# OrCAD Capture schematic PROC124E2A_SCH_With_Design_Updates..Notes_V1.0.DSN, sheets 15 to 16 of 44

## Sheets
15 11. PERIPHERAL POWER SUPPLY-2: size C; title: PERIPHERAL POWER SUPPLY-2
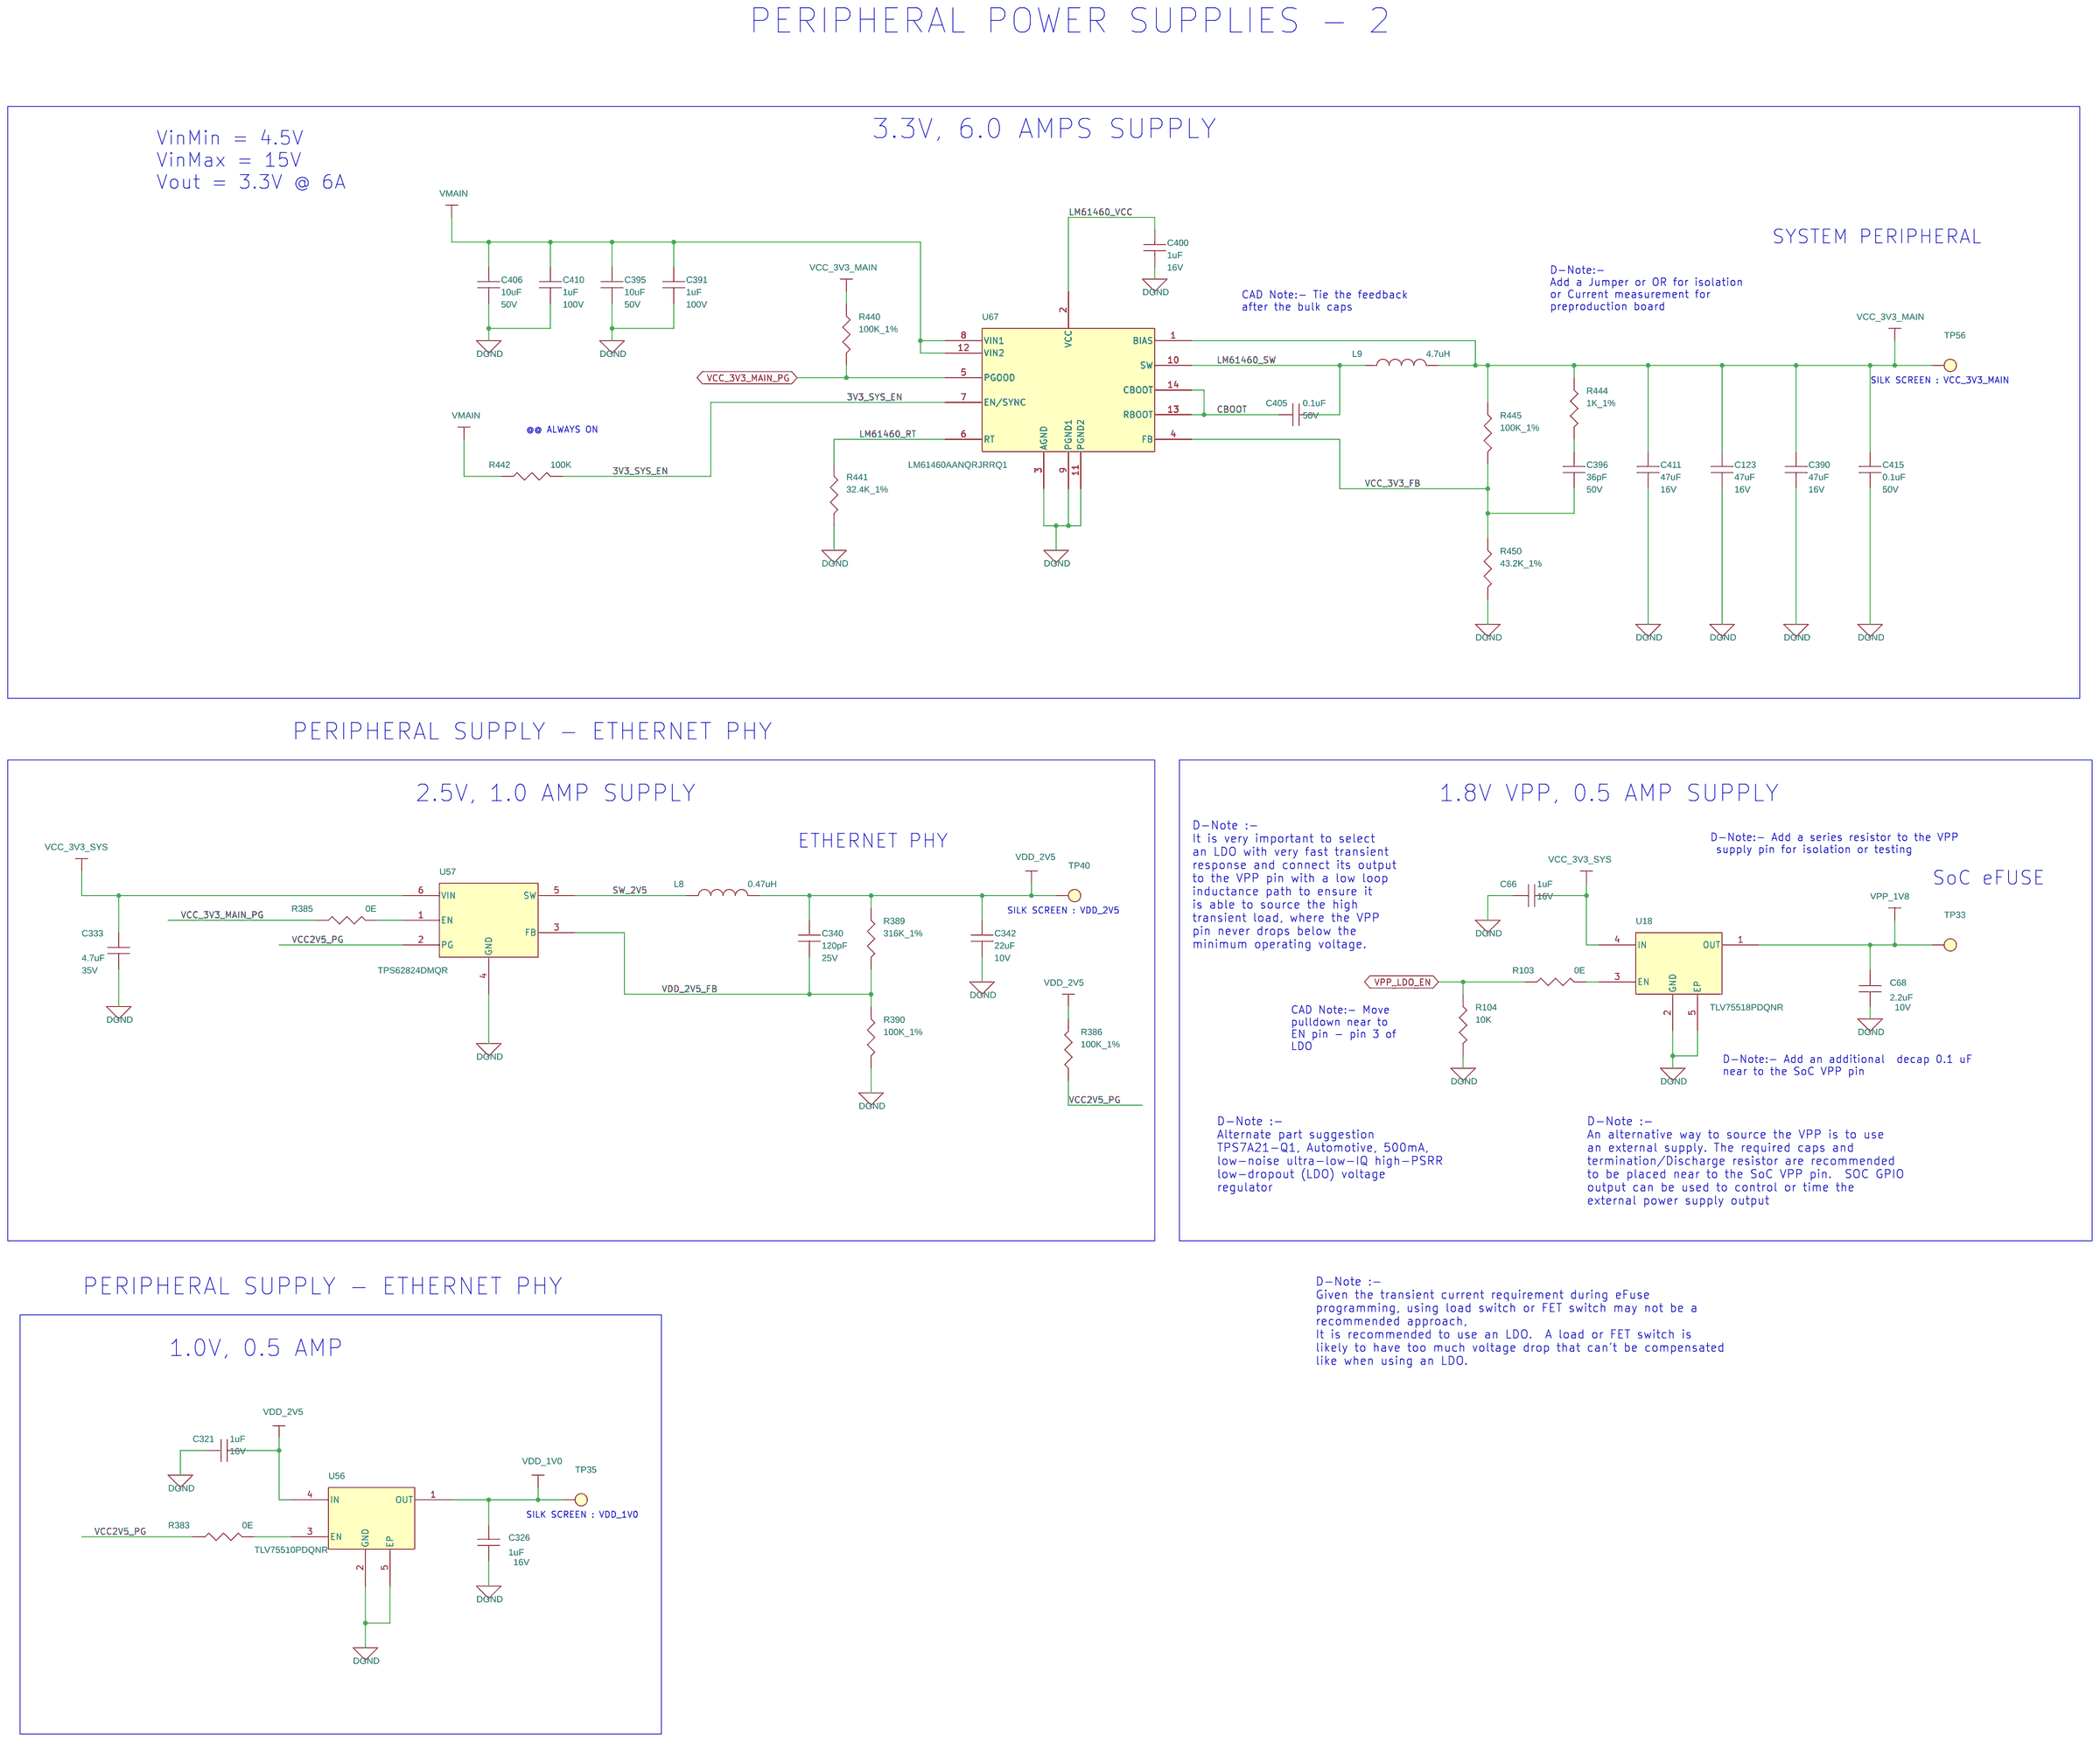
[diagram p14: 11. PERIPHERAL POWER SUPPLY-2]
16 13. CURRENT MONITORING DEVICES: size C; title: CURRENT MONITORING DEVICES
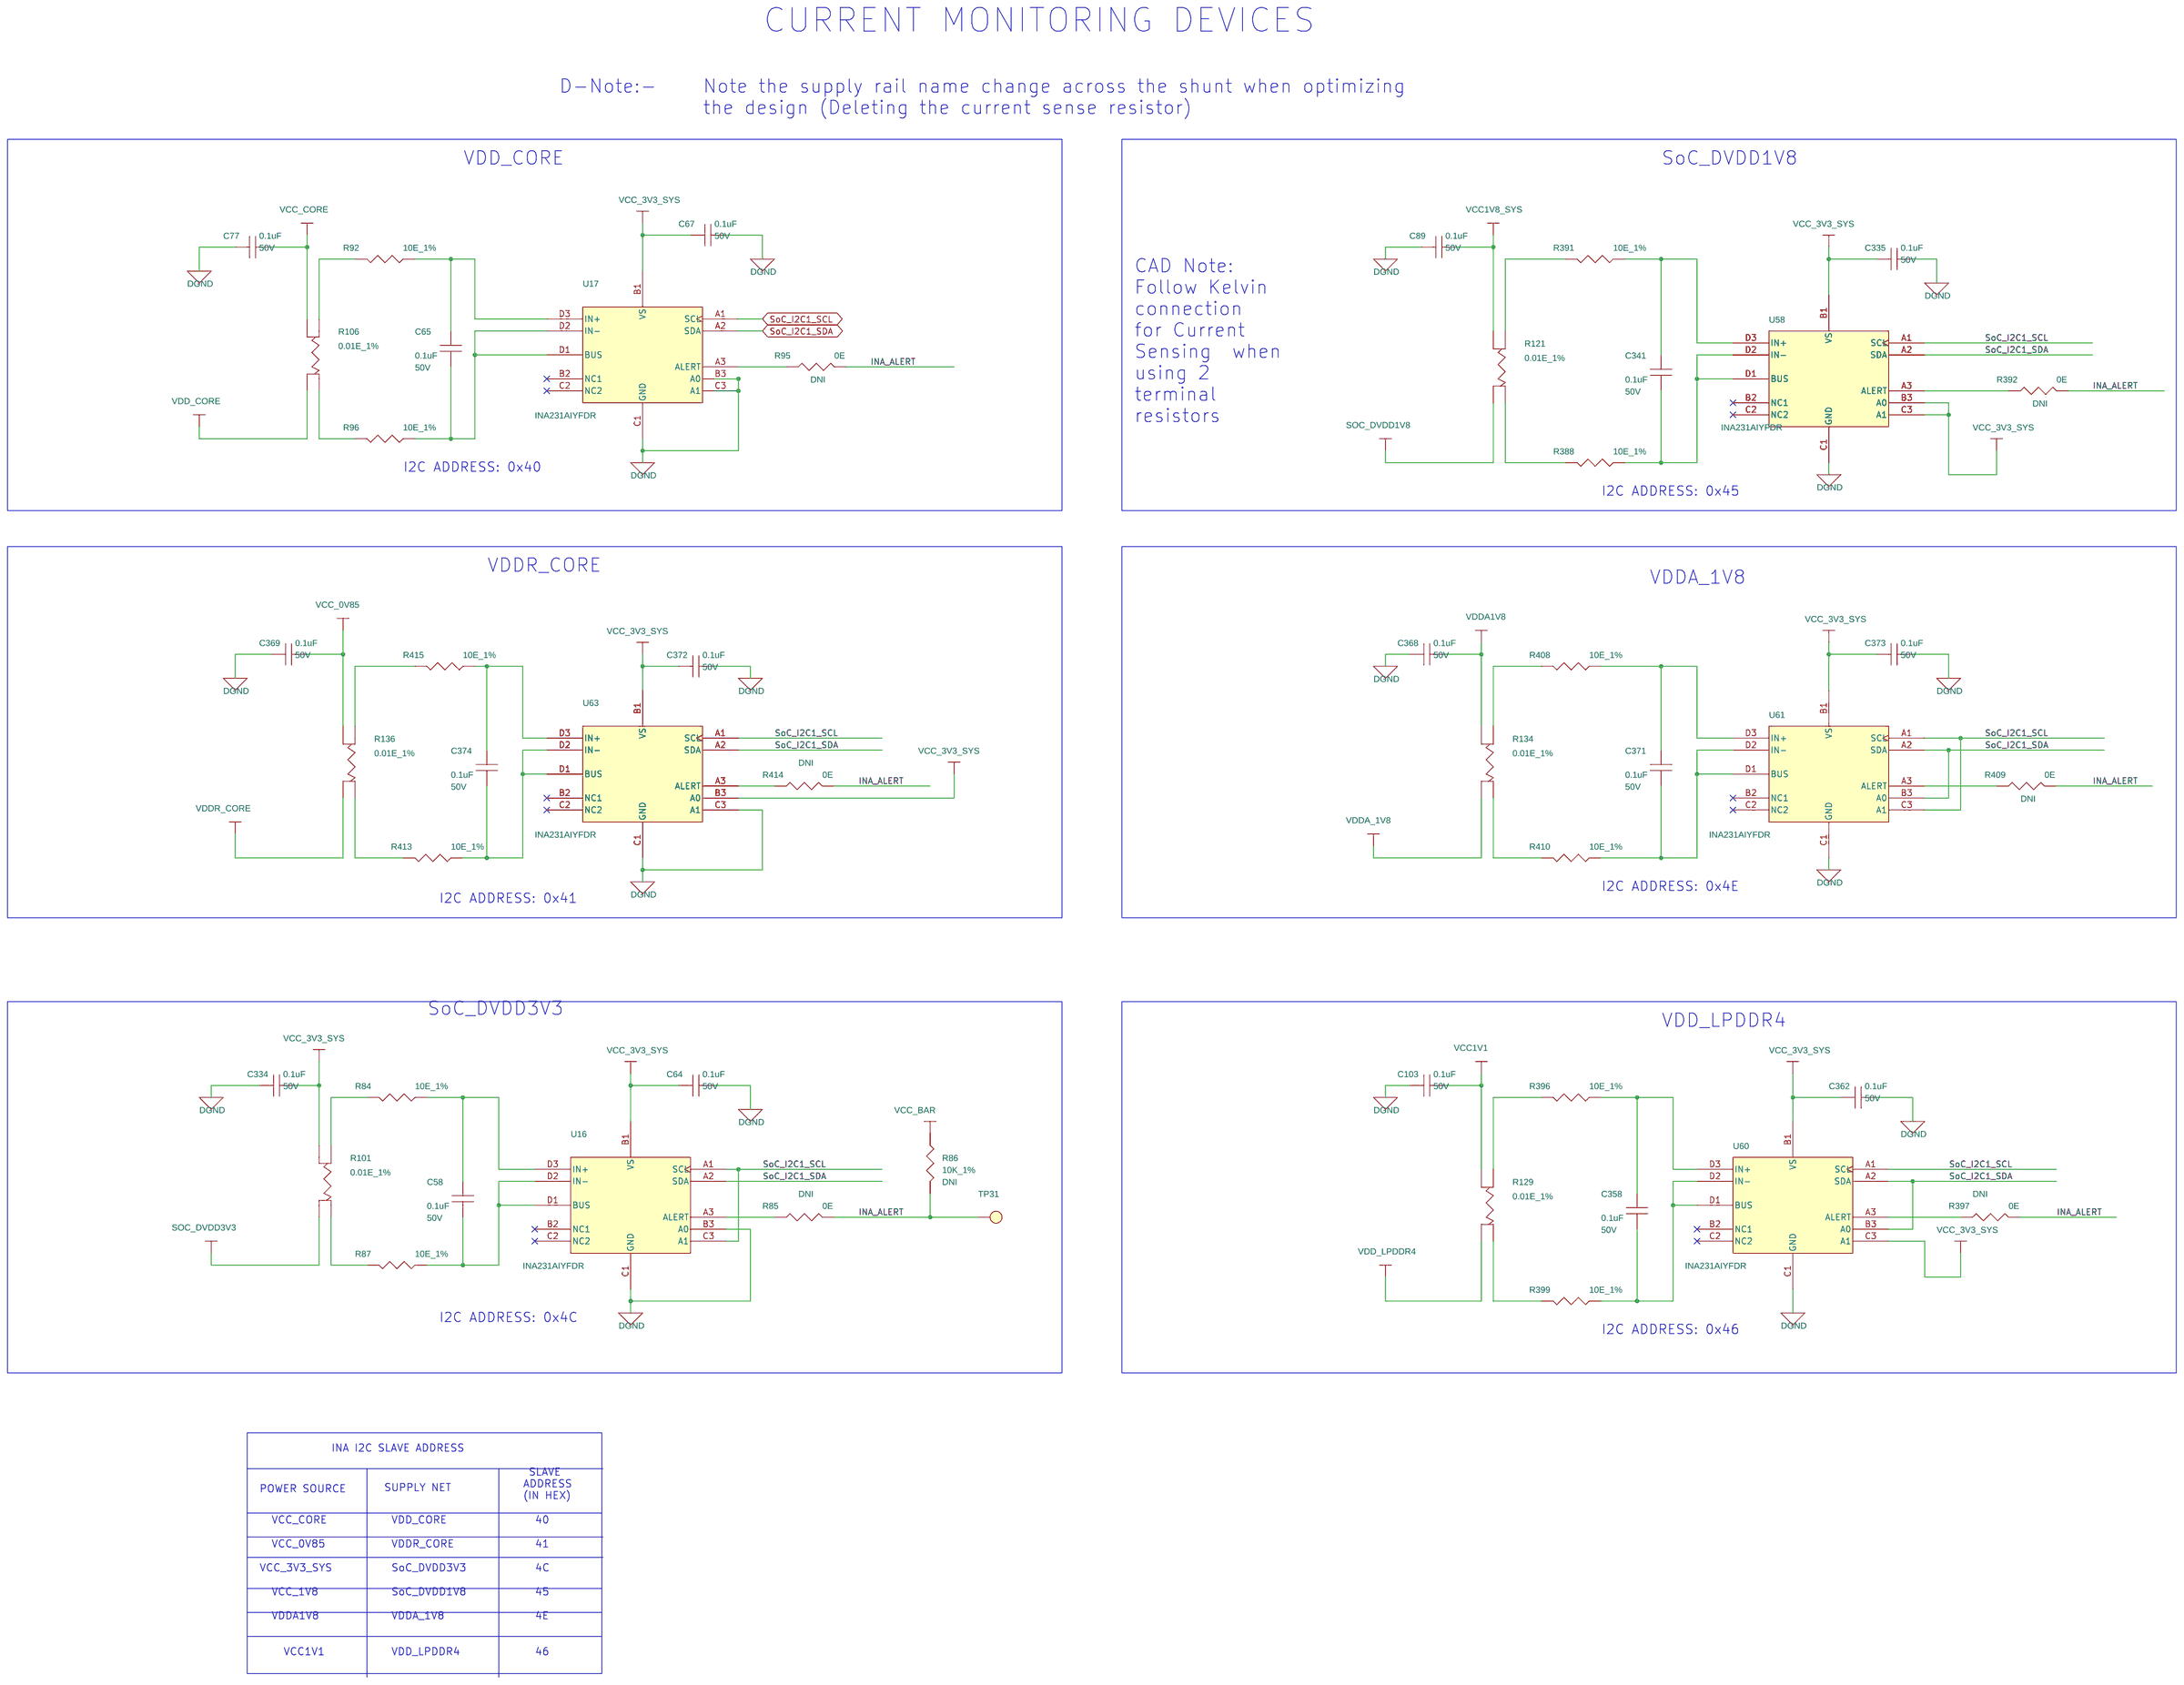
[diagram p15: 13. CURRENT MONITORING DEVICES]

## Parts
sheet 11. PERIPHERAL POWER SUPPLY-2
C66  1uF  [CAP0201_0-5]
C68  2.2uF  [CAP0201_0-5]
C123  47uF  [CAP1210_2-75]
C321  1uF  [CAP0201_0-5]
C326  1uF  [CAP0201_0-5]
C333  4.7uF  [CAP0603_1]
C340  120pF  [CAP0201_0-5]
C342  22uF  [CAP0603_1]
C390  47uF  [CAP1210_2-75]
C391  1uF  [CAP0805_1-5]
C395  10uF  [CAP0805_1-5]
C396  36pF  [CAP0402_0-75]
C400  1uF  [CAP0201_0-5]
C405  0.1uF  [CAP0402_0-75]
C406  10uF  [CAP0805_1-5]
C410  1uF  [CAP0805_1-5]
C411  47uF  [CAP1210_2-75]
C415  0.1uF  [CAP0402_0-75]
L8  0.47uH  [IND0806_1-2]
L9  4.7uH  [IND_XAL6060_260X270_SMD_6-1]
R103  0E  [RES0201_0-5]
R104  10K  [RES0201_0-5]
R383  0E  [RES0201_0-5]
R385  0E  [RES0201_0-5]
R386  100K_1%  [RES0402_0-5]
R389  316K_1%  [RES0402_0-5]
R390  100K_1%  [RES0402_0-5]
R440  100K_1%  [RES0402_0-5]
R441  32.4K_1%  [RES0402_0-5]
R442  100K  [RES0201_0-5]
R444  1K_1%  [RES0402_0-5]
R445  100K_1%  [RES0402_0-5]
R450  43.2K_1%  [RES0402_0-5]
TP33  TP20_SMD  [TP20_SMD]
TP35  TP20_SMD  [TP20_SMD]
TP40  TP20_SMD  [TP20_SMD]
TP56  TP20_SMD  [TP20_SMD]
U18  TLV75518PDQNR  [X2SON4_TLV71318P_40X40_0-4]
U56  TLV75510PDQNR  [X2SON4_TLV71318P_40X40_0-4]
U57  TPS62824DMQR  [VSONHR6_TPS62826_60X60_1]
U67  LM61460AANQRJRRQ1  [VQFNHR14_LM61460_160X140_1]
sheet 13. CURRENT MONITORING DEVICES
C58  0.1uF  [CAP0402_0-75]
C64  0.1uF  [CAP0402_0-75]
C65  0.1uF  [CAP0402_0-75]
C67  0.1uF  [CAP0402_0-75]
C77  0.1uF  [CAP0402_0-75]
C89  0.1uF  [CAP0402_0-75]
C103  0.1uF  [CAP0402_0-75]
C334  0.1uF  [CAP0402_0-75]
C335  0.1uF  [CAP0402_0-75]
C341  0.1uF  [CAP0402_0-75]
C358  0.1uF  [CAP0402_0-75]
C362  0.1uF  [CAP0402_0-75]
C368  0.1uF  [CAP0402_0-75]
C369  0.1uF  [CAP0402_0-75]
C371  0.1uF  [CAP0402_0-75]
C372  0.1uF  [CAP0402_0-75]
C373  0.1uF  [CAP0402_0-75]
C374  0.1uF  [CAP0402_0-75]
R84  10E_1%  [RES0402_0-5]
R85  0E  [RES0201_0-5]
R86  10K_1%  [RES0201_0-5]
R87  10E_1%  [RES0402_0-5]
R92  10E_1%  [RES0402_0-5]
R95  0E  [RES0201_0-5]
R96  10E_1%  [RES0402_0-5]
R101  0.01E_1%  [RES_KRL3216T4_1206-4_0-7]
R106  0.01E_1%  [RES_KRL3216T4_1206-4_0-7]
R121  0.01E_1%  [RES_KRL3216T4_1206-4_0-7]
R129  0.01E_1%  [RES_KRL3216T4_1206-4_0-7]
R134  0.01E_1%  [RES_KRL3216T4_1206-4_0-7]
R136  0.01E_1%  [RES_KRL3216T4_1206-4_0-7]
R388  10E_1%  [RES0402_0-5]
R391  10E_1%  [RES0402_0-5]
R392  0E  [RES0201_0-5]
R396  10E_1%  [RES0402_0-5]
R397  0E  [RES0201_0-5]
R399  10E_1%  [RES0402_0-5]
R408  10E_1%  [RES0402_0-5]
R409  0E  [RES0201_0-5]
R410  10E_1%  [RES0402_0-5]
R413  10E_1%  [RES0402_0-5]
R414  0E  [RES0201_0-5]
R415  10E_1%  [RES0402_0-5]
TP31  TP20_SMD  [TP20_SMD]
U16  INA231AIYFDR  [DSBGA12_15-74_60X70_0-4]
U17  INA231AIYFDR  [DSBGA12_15-74_60X70_0-4]
U58  INA231AIYFDR  [DSBGA12_15-74_60X70_0-4]
U60  INA231AIYFDR  [DSBGA12_15-74_60X70_0-4]
U61  INA231AIYFDR  [DSBGA12_15-74_60X70_0-4]
U63  INA231AIYFDR  [DSBGA12_15-74_60X70_0-4]

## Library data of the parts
C66 C321 C326 C400 = CAP: CAP CERAMIC 1uF 16V 20% X5R 0201; Chkd/date: MANIRAJA/300520; Crtd /date: ALVY/260520; Custom_Duty: 15%; Customs_HS_Code: 85322990; Distributor_name: DIGIKEY; Distributor_part_number: 490-18654-1-ND; Footprint Path: Y:\MIS_DATABASE\Library\ALTIUM_TOOL\PCB_FOOTPRINTS\Altium_Footprint_Lib.PcbLib; Height: 0.39MM; Library Path: Y:\MIS_DATABASE\Library\ALTIUM_TOOL\SCHEMATICS_PARTS\MS_DISCRETE_Library.schlib; Mfr_name: MURATA; Mfr_part_number: GRM033R61C105ME15D; Mistral Part No: 120018090038-R; Package: 0201; Part_type: CAPACITORS\CERAMIC; Project: QCS610_NANOSOM; RoHS: RoHS; Temperature: -55°C+85°C; Tolerance: 20%; Voltage: 16V; Wattage: NA; Weight: 0.33mg; Datasheet: Y:\MIS_DATABASE\DATASHEETS\CAPACITORS\GRM033R61C105ME15.PDF
C68 = CAP: CAP CERAMIC 2.2uF 10V 10% X5R 0201; Chkd/date: MANIRAJA/220918; Crtd /date: MANIRAJA/220918; Custom_Duty: 15%; Customs_HS_Code: 85322990; Distributor_name: DIGIKEY; Distributor_part_number: 490-13227-1-ND; Footprint Path: Y:\MIS_DATABASE\Library\ALTIUM_TOOL\PCB_FOOTPRINTS\Altium_Footprint_Lib.PcbLib; Height: 0.39MM; Library Path: Y:\MIS_DATABASE\Library\ALTIUM_TOOL\SCHEMATICS_PARTS\MS_DISCRETE_Library.schlib; Mfr_name: MURATA; Mfr_part_number: GRM033R61A225KE47D; Mistral Part No: 120018090044-R; Package: 0201; Part_type: CAPACITORS\CERAMIC; Project: TI_60GHz-AOP; RoHS: RoHS; Temperature: -55°C+85°C; Tolerance: 10%; Voltage: 10V; Wattage: NA; Weight: 0.33mg; Datasheet: Y:\MIS_DATABASE\DATASHEETS\CAPACITORS\GRM033R61A225KE47D.PDF
C123 C390 C411 = CAP: CAP CERAMIC 47uF 16V 10% X6S 1210; Chkd/date: ALVY/010721; Crtd /date: MANIRAJA/010721; Custom_Duty: 15%; Customs_HS_Code: 85322990; Distributor_name: DIGIKEY; Distributor_part_number: 490-10531-1-ND; Footprint Path: Y:\MIS_DATABASE\Library\ALTIUM_TOOL\PCB_FOOTPRINTS\Altium_Footprint_Lib.PcbLib; Height: 2.70MM; Library Path: Y:\MIS_DATABASE\Library\ALTIUM_TOOL\SCHEMATICS_PARTS\MS_DISCRETE_Library.schlib; Mfr_name: MURATA; Mfr_part_number: GRM32EC81C476KE15L; Mistral Part No: 120021070001-R; Package: 1210; Part_type: CAPACITORS\CERAMIC; Project: TI_AM263X_CC; RoHS: RoHS; Temperature: -55°C+105°C; Tolerance: 10%; Voltage: 16V; Wattage: NA; Weight: 100mg; Datasheet: Y:\MIS_DATABASE\DATASHEETS\CAPACITORS\GRM32EC81C476KE15.PDF
C333 = CAP: CAP CERAMIC 4.7uF 35V 20% X5R 0603; Chkd/date: MANIRAJA/120520; Crtd /date: ALVY/120520; Custom_Duty: 15%; Customs_HS_Code: 85322990; Distributor_name: DIGIKEY; Distributor_part_number: 490-11995-1-ND; Footprint Path: Y:\MIS_DATABASE\Library\ALTIUM_TOOL\PCB_FOOTPRINTS\Altium_Footprint_Lib.PcbLib; Height: 1.00MM; Library Path: Y:\MIS_DATABASE\Library\ALTIUM_TOOL\SCHEMATICS_PARTS\MS_DISCRETE_Library.schlib; Mfr_name: MURATA; Mfr_part_number: GRM188R6YA475ME15D; Mistral Part No: 120020050017-R; Package: 0603; Part_type: CAPACITORS\CERAMIC; Project: SD865_NANOSOM; RoHS: RoHS; Temperature: -55°C+85°C; Tolerance: 20%; Voltage: 35V; Wattage: NA; Weight: 6.3mg; Datasheet: Y:\MIS_DATABASE\DATASHEETS\CAPACITORS\GRM188R6YA475ME15.PDF
C340 = CAP: CAP CERAMIC 120pF 25V 10% X7R 0201; Chkd/date: ALVY/260821; Crtd /date: MANIRAJA/260821; Custom_Duty: 15%; Customs_HS_Code: 85322990; Distributor_name: DIGIKEY; Distributor_part_number: 490-3173-1-ND; Footprint Path: Y:\MIS_DATABASE\Library\ALTIUM_TOOL\PCB_FOOTPRINTS\Altium_Footprint_Lib.PcbLib; Height: 0.33MM; Library Path: Y:\MIS_DATABASE\Library\ALTIUM_TOOL\SCHEMATICS_PARTS\MS_DISCRETE_Library.schlib; Mfr_name: MURATA; Mfr_part_number: GRM033R71E121KA01D; Mistral Part No: 120021080009-R; Package: 0201; Part_type: CAPACITORS\CERAMIC; Project: TI_AM62x SKEVM_BRD; RoHS: RoHS; Temperature: -55°C+125°C; Tolerance: 10%; Voltage: 25V; Wattage: NA; Weight: 0.33mg; Datasheet: Y:\MIS_DATABASE\DATASHEETS\CAPACITORS\GRM033R71E121KA01.PDF
C342 = CAP: CAP CERAMIC 22uF 10V 20% X5R 0603; Chkd/date: MANIRAJA/230118; Crtd /date: MANIRAJA/230118; Custom_Duty: 15%; Customs_HS_Code: 85322990; Distributor_name: DIGIKEY; Distributor_part_number: 490-10476-1-ND; Footprint Path: Y:\MIS_DATABASE\Library\ALTIUM_TOOL\PCB_FOOTPRINTS\Altium_Footprint_Lib.PcbLib; Height: 1.00MM; Library Path: Y:\MIS_DATABASE\Library\ALTIUM_TOOL\SCHEMATICS_PARTS\MS_DISCRETE_Library.schlib; Mfr_name: MURATA; Mfr_part_number: GRM188R61A226ME15D; Mistral Part No: 120014100009-R; Package: 0603; Part_type: CAPACITORS\CERAMIC; Project: TI_MAXIE_CPB; RoHS: RoHS; Temperature: -55°C+85°C; Tolerance: 20%; Voltage: 10V; Wattage: NA; Weight: 6.3mg; Datasheet: Y:\MIS_DATABASE\DATASHEETS\CAPACITORS\GRM188R61A226ME15.PDF
C391 C410 = CAP: CAP CERAMIC 1uF 100V 10% X7S 0805; Chkd/date: MANIRAJA/160921; Crtd /date: ALVY/150921; Custom_Duty: 15%; Customs_HS_Code: 85322990; Distributor_name: DIGIKEY; Distributor_part_number: 490-14464-1-ND; Footprint Path: Y:\MIS_DATABASE\Library\ALTIUM_TOOL\PCB_FOOTPRINTS\Altium_Footprint_Lib.PcbLib; Height: 1.45MM; Library Path: Y:\MIS_DATABASE\Library\ALTIUM_TOOL\SCHEMATICS_PARTS\MS_DISCRETE_Library.schlib; Mfr_name: MURATA; Mfr_part_number: GRM21BC72A105KE01L; Mistral Part No: 120013030002-R; Package: 0805; Part_type: CAPACITORS\CERAMIC; Project: TI_AM62x SKEVM_BRD; RoHS: RoHS; Temperature: -55°C+125°C; Tolerance: 10%; Voltage: 100V; Wattage: NA; Weight: 6.4mg; Datasheet: Y:\MIS_DATABASE\DATASHEETS\CAPACITORS\GRM21BC72A105KE01.PDF
C395 C406 = CAP: CAP CERAMIC 10uF 50V 10% X5R 0805; Chkd/date: MANIRAJA/010321; Crtd /date: ALVY/010321; Custom_Duty: 15%; Customs_HS_Code: 85322990; Distributor_name: DIGIKEY; Distributor_part_number: 490-18663-1-ND; Footprint Path: Y:\MIS_DATABASE\Library\ALTIUM_TOOL\PCB_FOOTPRINTS\Altium_Footprint_Lib.PcbLib; Height: 1.45MM; Library Path: Y:\MIS_DATABASE\Library\ALTIUM_TOOL\SCHEMATICS_PARTS\MS_DISCRETE_Library.schlib; Mfr_name: MURATA; Mfr_part_number: GRM21BR61H106KE43L; Mistral Part No: 120021030002-R; Package: 0805; Part_type: CAPACITORS\CERAMIC; Project: J7ES_SK_BRD; RoHS: RoHS; Temperature: -55°C+85°C; Tolerance: 10%; Voltage: 50V; Wattage: NA; Weight: 6.4mg; Datasheet: Y:\MIS_DATABASE\DATASHEETS\CAPACITORS\GRM21BR61H106KE43.PDF
C396 = CAP: CAP CERAMIC 36pF 50V 2% HI-Q C0G(NP0) 0402; Chkd/date: MANIRAJA/061021; Crtd /date: ALVY/051021; Custom_Duty: 15%; Customs_HS_Code: 85322990; Distributor_name: DIGIKEY; Distributor_part_number: 490-GJM1555C1H360GB01DTR-ND; Footprint Path: Y:\MIS_DATABASE\Library\ALTIUM_TOOL\PCB_FOOTPRINTS\Altium_Footprint_Lib.PcbLib; Height: 0.55MM; Library Path: Y:\MIS_DATABASE\Library\ALTIUM_TOOL\SCHEMATICS_PARTS\MS_DISCRETE_Library.schlib; Mfr_name: MURATA; Mfr_part_number: GJM1555C1H360GB01D; Mistral Part No: 120021100002-R; Package: 0402; Part_type: CAPACITORS\CERAMIC; Project: TI_AM62x SKEVM_BRD; RoHS: RoHS; Temperature: -55°C+125°C; Tolerance: 2%; Voltage: 50V; Wattage: NA; Weight: 1.5mg; Datasheet: Y:\MIS_DATABASE\DATASHEETS\CAPACITORS\GJM1555C1H360GB01.PDF
C405 C415 = CAP: CAP CERAMIC 0.1uF 50V 10% X7R 0402; Chkd/date: MANIRAJA/261020; Crtd /date: ALVY/211020; Custom_Duty: 15%; Customs_HS_Code: 85322990; Distributor_name: DIGIKEY; Distributor_part_number: 490-10700-1-ND; Footprint Path: Y:\MIS_DATABASE\Library\ALTIUM_TOOL\PCB_FOOTPRINTS\Altium_Footprint_Lib.PcbLib; Height: 0.55MM; Library Path: Y:\MIS_DATABASE\Library\ALTIUM_TOOL\SCHEMATICS_PARTS\MS_DISCRETE_Library.schlib; Mfr_name: MURATA; Mfr_part_number: GRM155R71H104KE14D; Mistral Part No: 120011100014-R; Package: 0402; Part_type: CAPACITORS\CERAMIC; Project: J7_CP; RoHS: RoHS; Temperature: -55°C+125°C; Tolerance: 10%; Voltage: 50V; Wattage: NA; Weight: 3.1mg; Datasheet: Y:\MIS_DATABASE\DATASHEETS\CAPACITORS\GRM155R71H104KE14.PDF
L8 = INDUCTOR: IND CHIP 0.47uH 4.5A 20% 0806; Chkd/date: MANIRAJA/121020; Crtd /date: ALVY/121020; Custom_Duty: 24%; Customs_HS_Code: 85437099; Distributor_name: DIGIKEY; Distributor_part_number: DFE201612E-R47M=P2-ND; Footprint Path: Y:\MIS_DATABASE\Library\ALTIUM_TOOL\PCB_FOOTPRINTS\Altium_Footprint_Lib.PcbLib; Height: 1.20MM; Library Path: Y:\MIS_DATABASE\Library\ALTIUM_TOOL\SCHEMATICS_PARTS\MS_DISCRETE_Library.schlib; Mfr_name: MURATA; Mfr_part_number: DFE201612E-R47M=P2; Mistral Part No: 130020100030-R; Package: 0806; Project: AM64X_SKEVM; RoHS: RoHS; Temperature: -40°C+125°C; Tolerance: 20%; Voltage: NA; Wattage: NA; Weight: 18.8mg; Datasheet: Y:\MIS_DATABASE\DATASHEETS\DISCRETES\INDUCTORS\DFE201612E.PDF
L9 = INDUCTOR: IND POWER 4.7uH 11A 20% SMD; Chkd/date: VASANTHA/090317; Crtd /date: MANIRAJA/090317; Custom_Duty: 15%; Customs_HS_Code: 85412900; Distributor_name: MOUSER; Distributor_part_number: 994-XAL6060-472MEB; Footprint Path: Y:\MIS_DATABASE\Library\ALTIUM_TOOL\PCB_FOOTPRINTS\Altium_Footprint_Lib.PcbLib; Height: 6.10MM; Library Path: Y:\MIS_DATABASE\Library\ALTIUM_TOOL\SCHEMATICS_PARTS\MS_DISCRETE_Library.schlib; Mfr_name: COILCRAFT; Mfr_part_number: XAL6060-472MEB; Mistral Part No: 130015090013-R; Package: SMD; Project: OCTBTS_3000; RoHS: RoHS; Temperature: -40°C+125°C; Tolerance: 20%; Voltage: NA; Wattage: NA; Weight: 1600g; Datasheet: Y:\MIS_DATABASE\DATASHEETS\DISCRETES\INDUCTORS\XAL6060-SER.PDF
R103 R383 R385 = RESISTOR: RES 0E 1/20W 5% 0201; Chkd/date: NAVEED/301214; Crtd /date: MUDDU/120710; Custom_Duty: 15%; Customs_HS_Code: 85332119; Distributor_name: DIGIKEY; Distributor_part_number: 311-0.0NCT-ND; Footprint Path: Y:\MIS_DATABASE\Library\ALTIUM_TOOL\PCB_FOOTPRINTS\Altium_Footprint_Lib.PcbLib; Height: 0.26MM; Library Path: Y:\MIS_DATABASE\Library\ALTIUM_TOOL\SCHEMATICS_PARTS\MS_DISCRETE_Library.schlib; Mfr_name: YAGEO AMERICA; Mfr_part_number: RC0201JR-070RL; Mistral Part No: 110010070067-R; Package: 0201; Part_type: RESISTORS\FIXED; Project: PB_BUGBASE; RoHS: RoHS; Temperature: -55°C+125°C; Tolerance: 5%; Voltage: NA; Wattage: 1/20W; Weight: 0.17mg; Datasheet: Y:\MIS_DATABASE\DATASHEETS\RESISTORS\RCXXXXL-SER_MAR18.PDF
R104 = RESISTOR: RES 10K 1/20W 5% 0201; Chkd/date: MANIRAJA/050517; Crtd /date: MANIRAJA/050517; Custom_Duty: 15%; Customs_HS_Code: 85332119; Distributor_name: DIGIKEY; Distributor_part_number: 311-10KNCT-ND; Footprint Path: Y:\MIS_DATABASE\Library\ALTIUM_TOOL\PCB_FOOTPRINTS\Altium_Footprint_Lib.PcbLib; Height: 0.26MM; Library Path: Y:\MIS_DATABASE\Library\ALTIUM_TOOL\SCHEMATICS_PARTS\MS_DISCRETE_Library.schlib; Mfr_name: YAGEO AMERICA; Mfr_part_number: RC0201JR-0710KL; Mistral Part No: 110010070051-R; Package: 0201; Part_type: RESISTORS\FIXED; Project: GOLDEN-I LITE; RoHS: RoHS; Temperature: -55°C+125°C; Tolerance: 5%; Voltage: NA; Wattage: 1/20W; Weight: 0.17mg; Datasheet: Y:\MIS_DATABASE\DATASHEETS\RESISTORS\RCXXXXL-SER_MAR18.PDF
R386 R390 R440 R445 = RESISTOR: RES 100K 1/10W 1% 0402; Chkd/date: VASANTHA/201216; Crtd /date: MAZHAR/130306; Custom_Duty: 15%; Customs_HS_Code: 85332119; Distributor_name: DIGIKEY; Distributor_part_number: P100KLCT-ND; Footprint Path: Y:\MIS_DATABASE\Library\ALTIUM_TOOL\PCB_FOOTPRINTS\Altium_Footprint_Lib.PcbLib; Height: 0.40MM; Library Path: Y:\MIS_DATABASE\Library\ALTIUM_TOOL\SCHEMATICS_PARTS\MS_DISCRETE_Library.schlib; Mfr_name: PANASONIC-ECG; Mfr_part_number: ERJ-2RKF1003X; Mistral Part No: 110009030187-R; Package: 0402; Part_type: RESISTORS\FIXED; Project: J32; RoHS: RoHS; Temperature: -55°C+155°C; Tolerance: 1%; Voltage: NA; Wattage: 1/10W; Weight: 0.8mg; Datasheet: Y:\MIS_DATABASE\DATASHEETS\RESISTORS\PAN-ERJSER_NOV17.PDF
R389 = RESISTOR: RES 316K 1/10W 1% 0402; Chkd/date: MAZHAR/110310; Crtd /date: MUDDU/080310; Custom_Duty: 15%; Customs_HS_Code: 85332119; Distributor_name: DIGIKEY; Distributor_part_number: P316KLCT-ND; Footprint Path: Y:\MIS_DATABASE\Library\ALTIUM_TOOL\PCB_FOOTPRINTS\Altium_Footprint_Lib.PcbLib; Height: 0.40MM; Library Path: Y:\MIS_DATABASE\Library\ALTIUM_TOOL\SCHEMATICS_PARTS\MS_DISCRETE_Library.schlib; Mfr_name: PANASONIC-ECG; Mfr_part_number: ERJ-2RKF3163X; Mistral Part No: 110010030027-R; Package: 0402; Part_type: RESISTORS\FIXED; Project: VME_DSP_SUITE; RoHS: RoHS; Temperature: -55°C+155°C; Tolerance: 1%; Voltage: NA; Wattage: 1/10W; Weight: 0.8mg; Datasheet: Y:\MIS_DATABASE\DATASHEETS\RESISTORS\PAN-ERJSER_NOV17.PDF
R441 = RESISTOR: RES 32.4K 1/16W 1% 0402; Chkd/date: MANIRAJA/080420; Crtd /date: ALVY/080420; Custom_Duty: 15%; Customs_HS_Code: 85332119; Distributor_name: DIGIKEY; Distributor_part_number: 541-32.4KLCT-ND; Footprint Path: Y:\MIS_DATABASE\Library\ALTIUM_TOOL\PCB_FOOTPRINTS\Altium_Footprint_Lib.PcbLib; Height: 0.40MM; Library Path: Y:\MIS_DATABASE\Library\ALTIUM_TOOL\SCHEMATICS_PARTS\MS_DISCRETE_Library.schlib; Mfr_name: VISHAY; Mfr_part_number: CRCW040232K4FKED; Mistral Part No: 110020040003-R; Package: 0402; Part_type: RESISTORS\FIXED; Project: HSDTRS_FEE_BRD; RoHS: RoHS; Temperature: -55°C+155°C; Tolerance: 1%; Voltage: NA; Wattage: 1/16W; Weight: 0.65mg; Datasheet: Y:\MIS_DATABASE\DATASHEETS\RESISTORS\CRCW0603.PDF
R442 = RESISTOR: RES 100K 1/20W 5% 0201; Chkd/date: PRAVEEN/080922; Crtd /date: TAMILARASU/080922; Custom_Duty: 15%; Customs_HS_Code: 85332119; Distributor_name: DIGIKEY; Distributor_part_number: P123223CT-ND; Footprint Path: Y:\MIS_DATABASE\Library\ALTIUM_TOOL\PCB_FOOTPRINTS\Altium_Footprint_Lib.PcbLib; Height: 0.26MM; Library Path: Y:\MIS_DATABASE\Library\ALTIUM_TOOL\SCHEMATICS_PARTS\MS_DISCRETE_Library.schlib; Mfr_name: PANASONIC-ECG; Mfr_part_number: ERJ-1GNJ104C; Mistral Part No: 110022090005-R; Package: 0201; Part_type: RESISTORS\FIXED; Project: SK AM62Q LP EVM BRD; RoHS: RoHS; Temperature: -55°C+125°C; Tolerance: 5%; Voltage: NA; Wattage: 1/20W; Weight: 0.15mg; Datasheet: Y:\MIS_DATABASE\DATASHEETS\RESISTORS\PAN-ERJSER_NOV17.PDF
R444 = RESISTOR: RES 1K 1/10W 1% 0402; Chkd/date: VASANTHA/281216; Crtd /date: MAZHAR/150506; Custom_Duty: 15%; Customs_HS_Code: 85332119; Distributor_name: DIGIKEY; Distributor_part_number: P1.00KLCT-ND; Footprint Path: Y:\MIS_DATABASE\Library\ALTIUM_TOOL\PCB_FOOTPRINTS\Altium_Footprint_Lib.PcbLib; Height: 0.40MM; Library Path: Y:\MIS_DATABASE\Library\ALTIUM_TOOL\SCHEMATICS_PARTS\MS_DISCRETE_Library.schlib; Mfr_name: PANASONIC-ECG; Mfr_part_number: ERJ-2RKF1001X; Mistral Part No: 110009030411-R; Package: 0402; Part_type: RESISTORS\FIXED; Project: VOCERA; RoHS: RoHS; Temperature: -55°C+155°C; Tolerance: 1%; Voltage: NA; Wattage: 1/10W; Weight: 0.8mg; Datasheet: Y:\MIS_DATABASE\DATASHEETS\RESISTORS\PAN-ERJSER_NOV17.PDF
R450 = RESISTOR: RES 43.2K 1/16W 1% 0402; Chkd/date: MANIRAJA/250821; Crtd /date: ALVY/250821; Custom_Duty: 15%; Customs_HS_Code: 85332119; Distributor_name: DIGIKEY; Distributor_part_number: 541-43.2KLCT-ND; Footprint Path: Y:\MIS_DATABASE\Library\ALTIUM_TOOL\PCB_FOOTPRINTS\Altium_Footprint_Lib.PcbLib; Height: 0.40MM; Library Path: Y:\MIS_DATABASE\Library\ALTIUM_TOOL\SCHEMATICS_PARTS\MS_DISCRETE_Library.schlib; Mfr_name: VISHAY; Mfr_part_number: CRCW040243K2FKED; Mistral Part No: 110021080019-R; Package: 0402; Part_type: RESISTORS\FIXED; Project: TI_AM62x SKEVM_BRD; RoHS: RoHS; Temperature: -55°C+155°C; Tolerance: 1%; Voltage: NA; Wattage: 1/16W; Weight: 0.65mg; Datasheet: Y:\MIS_DATABASE\DATASHEETS\RESISTORS\CRCW0603.PDF
TP33 TP35 TP40 TP56 = TESTPOINT: TESTPOINT CIR 20 SMD; Chkd/date: SHREESHAIL/171006; Crtd /date: MAZHAR/171006; Custom_Duty: NA; Customs_HS_Code: NA; Distributor_name: NA; Distributor_part_number: NA; Footprint Path: Y:\MIS_DATABASE\Library\ALTIUM_TOOL\PCB_FOOTPRINTS\Altium_Footprint_Lib.PcbLib; Height: NA; Library Path: Y:\MIS_DATABASE\Library\ALTIUM_TOOL\SCHEMATICS_PARTS\MS_DISCRETE_Library.schlib; MECHANICAL 3D STEP FILE: NA; Manufacturer: LOCAL; Mfr_name: LOCAL; Mistral Part No: NA; Package: SMD; Project: BT MODULE_CSRBC04; RoHS: NA; Temperature: NA; Tolerance: NA; Voltage: NA; Wattage: NA; Weight: NA; Datasheet: NA
U18 = TLV71318PDQNR_X2SON4: IC 500mA LOW IQ LDO REGULATOR X2SON-4; Chkd/date: MANIRAJA/170620; Crtd /date: ALVY/160620; Custom_Duty: 15%; Customs_HS_Code: 85423100; Distributor_name: DIGIKEY; Distributor_part_number: 296-51790-1-ND; Footprint Path: Y:\MIS_DATABASE\Library\ALTIUM_TOOL\PCB_FOOTPRINTS\Altium_Footprint_Lib.PcbLib; Height: 0.40MM; Library Path: Y:\MIS_DATABASE\Library\ALTIUM_TOOL\SCHEMATICS_PARTS\MS_MISCPOWER_Library.schlib; Mfr_name: TEXAS INSTRUMENTS; Mistral Part No: 142020060013-R; Package: X2SON-4; Part_type: ICS\POWER\VOLTAGE REGULATOR; Project: AM64x-GP_EVM BRD; RoHS: RoHS; Temperature: -40°C+125°C; Tolerance: NA; Voltage: NA; Wattage: NA; Weight: 1.1mg; Datasheet: Y:\MIS_DATABASE\DATASHEETS\ICS\POWER\TLV755P.PDF
U56 = TLV71318PDQNR_X2SON4: IC 500mA 1V LOW IQ LDO REGULATOR X2SON-4; Chkd/date: MANIRAJA/240821; Crtd /date: ALVY/240821; Custom_Duty: 15%; Customs_HS_Code: 85423100; Distributor_name: DIGIKEY; Distributor_part_number: 296-51782-1-ND; Footprint Path: Y:\MIS_DATABASE\Library\ALTIUM_TOOL\PCB_FOOTPRINTS\Altium_Footprint_Lib.PcbLib; Height: 0.40MM; Library Path: Y:\MIS_DATABASE\Library\ALTIUM_TOOL\SCHEMATICS_PARTS\MS_MISCPOWER_Library.schlib; Mfr_name: TEXAS INSTRUMENTS; Mistral Part No: 142021080018-R; Package: X2SON-4; Part_type: ICS\POWER\VOLTAGE REGULATOR; Project: TI_AM62x SKEVM_BRD; RoHS: RoHS; Temperature: -40°C+125°C; Tolerance: NA; Voltage: NA; Wattage: NA; Weight: 1.1mg; Datasheet: Y:\MIS_DATABASE\DATASHEETS\ICS\POWER\TLV755P.PDF
U57 = TPS62827DMQR_VSONHR6: IC 1A ADJ STEP-DOWN CONVERTER WITH 1% OUTPUT ACCURACY VSON-HR6; Chkd/date: ALVY/071021; Crtd /date: MANIRAJA/071021; Custom_Duty: 15%; Customs_HS_Code: 85423100; Distributor_name: NA; Distributor_part_number: NA; Footprint Path: Y:\MIS_DATABASE\Library\ALTIUM_TOOL\PCB_FOOTPRINTS\Altium_Footprint_Lib.PcbLib; Height: 1.00MM; Library Path: Y:\MIS_DATABASE\Library\ALTIUM_TOOL\SCHEMATICS_PARTS\MS_MISCPOWER_Library.schlib; Mfr_name: TEXAS INSTRUMENTS; Mistral Part No: 142021100006-R; Package: VSON-HR6; Part_type: ICS\POWER\DC-DC CONVERTER; Project: TI_AM62x SKEVM_BRD; RoHS: RoHS; Temperature: -40°C+125°C; Tolerance: NA; Voltage: NA; Wattage: NA; Weight: NA; Datasheet: Y:\MIS_DATABASE\DATASHEETS\ICS\POWER\TPS6282XX-DEC2020.PDF
U67 = LM61460_VQFNHR14: IC 6A ADJ AUTO LOW EMI SYNCHRONOUS STEP DOWN DC-DC CONVERTER VQFN-HR14; Chkd/date: ALVY/040221; Crtd /date: MANIRAJA/030221; Custom_Duty: 15%; Customs_HS_Code: 85423100; Distributor_name: DIGIKEY; Distributor_part_number: 296-LM61460AANQRJRRQ1TR-ND; Footprint Path: Y:\MIS_DATABASE\Library\ALTIUM_TOOL\PCB_FOOTPRINTS\Altium_Footprint_Lib.PcbLib; Height: 1.00MM; Library Path: Y:\MIS_DATABASE\Library\ALTIUM_TOOL\SCHEMATICS_PARTS\MS_MISCPOWER_Library.schlib; Mfr_name: TEXAS INSTRUMENTS; Mistral Part No: 142021020006-R; Package: VQFN-HR14; Part_type: ICS\POWER\DC-DC CONVERTER; Project: J7ES_SK_BRD; RoHS: RoHS; Temperature: -40°C+150°C; Tolerance: NA; Voltage: NA; Wattage: NA; Weight: NA; Datasheet: Y:\MIS_DATABASE\DATASHEETS\ICS\POWER\LM61460-Q1.PDF
C58 C64 C65 C67 C77 C89 C103 C334 C335 C341 C358 C362 C368 C369 C371-C374 = CAP: CAP CERAMIC 0.1uF 50V 10% X7R 0402; Alt_Mfr_name: YAGEO AMERICA; Alt_Mfr_part_number: CC0402KRX5R8BB104; Chkd/date: MANIRAJA/261020; Crtd /date: ALVY/211020; Custom_Duty: 15%; Customs_HS_Code: 85322990; Distributor_name: DIGIKEY; Distributor_part_number: 490-10700-1-ND; Footprint Path: Y:\MIS_DATABASE\Library\ALTIUM_TOOL\PCB_FOOTPRINTS\Altium_Footprint_Lib.PcbLib; Height: 0.55MM; Library Path: Y:\MIS_DATABASE\Library\ALTIUM_TOOL\SCHEMATICS_PARTS\MS_DISCRETE_Library.schlib; Mfr_name: MURATA; Mfr_part_number: GRM155R71H104KE14D; Mistral Part No: 120011100014-R; Package: 0402; Part_type: CAPACITORS\CERAMIC; Project: J7_CP; RoHS: RoHS; Temperature: -55°C+125°C; Tolerance: 10%; Voltage: 50V; Wattage: NA; Weight: 3.1mg; Datasheet: Y:\MIS_DATABASE\DATASHEETS\CAPACITORS\GRM155R71H104KE14.PDF
R84 R87 R92 R96 R388 R391 R396 R399 R408 R410 R413 R415 = RESISTOR: RES 10E 1/16W 1% 0402; Chkd/date: MANIRAJA/070218; Crtd /date: ALVY/070218; Custom_Duty: 15%; Customs_HS_Code: 85332119; Distributor_name: DIGIKEY; Distributor_part_number: 311-10.0LRCT-ND; Footprint Path: Y:\MIS_DATABASE\Library\ALTIUM_TOOL\PCB_FOOTPRINTS\Altium_Footprint_Lib.PcbLib; Height: 0.40MM; Library Path: Y:\MIS_DATABASE\Library\ALTIUM_TOOL\SCHEMATICS_PARTS\MS_DISCRETE_Library.schlib; Mfr_name: YAGEO AMERICA; Mfr_part_number: RC0402FR-0710RL; Mistral Part No: 110018020004-R; Package: 0402; Part_type: RESISTORS\FIXED; Project: TI_MAXIE_CPB; RoHS: RoHS; Temperature: -55°C+155°C; Tolerance: 1%; Voltage: NA; Wattage: 1/16W; Weight: 0.65mg; Datasheet: Y:\MIS_DATABASE\DATASHEETS\RESISTORS\RCXXXXL-SER_MAR18.PDF
R85 R95 R392 R397 R409 R414 = RESISTOR: RES 0E 1/20W 5% 0201; Assembly_Instruction: DNI; Chkd/date: NAVEED/301214; Crtd /date: MUDDU/120710; Custom_Duty: 15%; Customs_HS_Code: 85332119; Distributor_name: DIGIKEY; Distributor_part_number: 311-0.0NCT-ND; Footprint Path: Y:\MIS_DATABASE\Library\ALTIUM_TOOL\PCB_FOOTPRINTS\Altium_Footprint_Lib.PcbLib; Height: 0.26MM; Library Path: Y:\MIS_DATABASE\Library\ALTIUM_TOOL\SCHEMATICS_PARTS\MS_DISCRETE_Library.schlib; Mfr_name: YAGEO AMERICA; Mfr_part_number: RC0201JR-070RL; Mistral Part No: 110010070067-R; Package: 0201; Part_type: RESISTORS\FIXED; Project: PB_BUGBASE; RoHS: RoHS; Temperature: -55°C+125°C; Tolerance: 5%; Voltage: NA; Wattage: 1/20W; Weight: 0.17mg; Datasheet: Y:\MIS_DATABASE\DATASHEETS\RESISTORS\RCXXXXL-SER_MAR18.PDF
R86 = RESISTOR: RES 10K 1/20W 1% 0201; Assembly_Instruction: DNI; Chkd/date: VASANTHA/270117; Crtd /date: MANIRAJA/270117; Custom_Duty: 15%; Customs_HS_Code: 85332119; Distributor_name: DIGIKEY; Distributor_part_number: 311-10.0KMCT-ND; Footprint Path: Y:\MIS_DATABASE\Library\ALTIUM_TOOL\PCB_FOOTPRINTS\Altium_Footprint_Lib.PcbLib; Height: 0.26MM; Library Path: Y:\MIS_DATABASE\Library\ALTIUM_TOOL\SCHEMATICS_PARTS\MS_DISCRETE_Library.schlib; Mfr_name: YAGEO AMERICA; Mfr_part_number: RC0201FR-0710KL; Mistral Part No: 110011040018-R; Package: 0201; Part_type: RESISTORS\FIXED; Project: GOLDEN-I LITE; RoHS: RoHS; Temperature: -55°C+125°C; Tolerance: 1%; Voltage: NA; Wattage: 1/20W; Weight: 0.17mg; Datasheet: Y:\MIS_DATABASE\DATASHEETS\RESISTORS\RCXXXXL-SER_MAR18.PDF
R101 R106 R121 R129 R134 R136 = RESISTOR-4TERM: RES 0.01E 1W 1% 1206-4; Chkd/date: MANIRAJA/060318; Crtd /date: MANIRAJA/060318; Custom_Duty: 15%; Customs_HS_Code: 85332119; Distributor_name: DIGIKEY; Distributor_part_number: 408-1974-1-ND; Footprint Path: Y:\MIS_DATABASE\Library\ALTIUM_TOOL\PCB_FOOTPRINTS\Altium_Footprint_Lib.PcbLib; Height: 0.70MM; Library Path: Y:\MIS_DATABASE\Library\ALTIUM_TOOL\SCHEMATICS_PARTS\MS_DISCRETE_Library.schlib; Manufacturer: SUSUMU; Mfr_name: SUSUMU; Mfr_part_number: KRL3216T4A-M-R010-F-T1; Mistral Part No: 110018030003-R; Package: 1206-4; Part_type: RESISTORS\FIXED; Project: GRACO SMART MODULE; RoHS: RoHS; Temperature: -55°C+155°C; Tolerance: 1%; Voltage: NA; Wattage: 1W; Weight: 16.2mg; Datasheet: Y:\MIS_DATABASE\DATASHEETS\RESISTORS\KRL-SERIES.PDF
TP31 = TESTPOINT: TESTPOINT CIR 20 SMD; Chkd/date: SHREESHAIL/171006; Crtd /date: MAZHAR/171006; Custom_Duty: NA; Customs_HS_Code: NA; Distributor_name: NA; Distributor_part_number: NA; Footprint Path: Y:\MIS_DATABASE\Library\ALTIUM_TOOL\PCB_FOOTPRINTS\Altium_Footprint_Lib.PcbLib; Height: NA; Library Path: Y:\MIS_DATABASE\Library\ALTIUM_TOOL\SCHEMATICS_PARTS\MS_DISCRETE_Library.schlib; MECHANICAL 3D STEP FILE: NA; Mfr_name: LOCAL; Mistral Part No: NA; Package: SMD; Project: BT MODULE_CSRBC04; RoHS: NA; Temperature: NA; Tolerance: NA; Voltage: NA; Wattage: NA; Weight: NA; Datasheet: NA
U16 U17 U58 U60 U61 U63 = INA231_DSBGA12: IC HIGH OR LOW SIDE MEASUREMENT BI-DIR CURRENT AND POWER MONITOR WITH 1.8V I2C INTERFACE DSBGA12; Chkd/date: MANIRAJA/250821; Crtd /date: ALVY/250821; Custom_Duty: 15%; Customs_HS_Code: 85423100; Distributor_name: DIGIKEY; Distributor_part_number: 296-49645-1-ND; Footprint Path: Y:\MIS_DATABASE\Library\ALTIUM_TOOL\PCB_FOOTPRINTS\Altium_Footprint_Lib.PcbLib; Height: 0.40MM; Library Path: Y:\MIS_DATABASE\Library\ALTIUM_TOOL\SCHEMATICS_PARTS\MS_MISCPOWER_Library.schlib; Mfr_name: TEXAS INSTRUMENTS; Mistral Part No: 142021080022-R; Package: DSBGA12; Part_type: ICS\POWER\MANAGEMENT; Project: TI_AM62x SVB_BRD; RoHS: RoHS; Temperature: -40°C+125°C; Tolerance: NA; Voltage: NA; Wattage: NA; Weight: 200mg; Datasheet: Y:\MIS_DATABASE\DATASHEETS\ICS\POWER\INA231XXX.PDF

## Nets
3V3_SYS_EN: R442.2 U67.7(EN/SYNC)
DGND: C64.2 C66.2 C67.2 C68.1 C77.1 C89.1 C103.1 C123.2 C321.2 C326.2 C333.2 C334.1 C335.2 C342.2 C362.2 C368.1 C369.1 C372.2 C373.2 C390.2 C391.2 C395.2 C400.2 C406.2 C410.2 C411.2 C415.2 R104.2 R390.2 R441.2 R450.2 U16.B3(A0) U16.C1(GND) U17.B3(A0) U17.C1(GND) U17.C3(A1) U18.2(GND) U18.5(EP) U56.2(GND) U56.5(EP) U57.4(GND) U58.C1(GND) U60.C1(GND) U61.C1(GND) U63.C1(GND) U63.C3(A1) U67.3(AGND) U67.9(PGND1) U67.11(PGND2) ; also on sheet 1 2 3 4 13 14 17 18 19 20 21 22 23 24 25 26 27 28 29 30 31 32 33 34 35 36 37 38 39 40 41 42 43
VCC1V1: C103.2 R129.2 ; also on sheet 4
VCC1V8_SYS: C89.2 R121.2 ; also on sheet 4 19 20 22 25 34 37 39 40 42
VCC2V5_PG: R383.1 R386.1 U57.2(PG)
VCC_0V85: C369.2 R136.2 ; also on sheet 4
VCC_3V3_FB: C396.2 R445.2 R450.1 U67.4(FB)
VCC_3V3_MAIN: C123.1 C390.1 C411.1 C415.1 L9.2 R440.1 R444.1 R445.1 TP56.1(TP) U67.1(BIAS) ; also on sheet 4 17
VCC_3V3_MAIN_PG: R385.1 R440.2 U67.5(PGOOD) ; also on sheet 4
VCC_3V3_SYS: C64.1 C66.1 C67.1 C333.1 C334.2 C335.1 C362.1 C372.1 C373.1 R86.2 R101.2 U16.B1(VS) U17.B1(VS) U18.4(IN) U57.6(VIN) U58.B1(VS) U58.B3(A0) U58.C3(A1) U60.B1(VS) U60.C3(A1) U61.B1(VS) U63.B1(VS) U63.B3(A0) ; also on sheet 1 4 19 20 21 23 24 26 27 29 30 31 32 33 34 36 37 38 39 40 41 42 43
VCC_CORE: C77.2 R106.2 ; also on sheet 4
VDD_1V0: C326.1 TP35.1(TP) U56.1(OUT) ; also on sheet 1 24
VDD_2V5: C321.1 C340.1 C342.1 L8.2 R386.2 R389.1 TP40.1(TP) U56.4(IN) ; also on sheet 1 24
VDD_2V5_FB: C340.2 R389.2 R390.1 U57.3(FB)
VDD_CORE: R106.3 ; also on sheet 17 18
VDD_LPDDR4: R129.3 ; also on sheet 3 17 18
VDDA1V8: C368.2 R134.2 ; also on sheet 4
VDDA_1V8: R134.3 ; also on sheet 17
VDDR_CORE: R136.3 ; also on sheet 17 18 36
CBOOT: C405.1 U67.13(RBOOT) U67.14(CBOOT)
INA_ALERT: R85.2 R86.1 R95.2 R392.2 R397.2 R409.2 R414.2 TP31.1(TP)
LM61460_RT: R441.1 U67.6(RT)
LM61460_SW: C405.2 L9.1 U67.10(SW)
LM61460_VCC: C400.1 U67.2(VCC)
SOC_DVDD1V8: R121.3 ; also on sheet 3 17 18
SoC_DVDD3V3: R101.3 ; also on sheet 17 18
SOC_I2C1_SCL: U16.A1(SCL) U16.C3(A1) U17.A1(SCL) U58.A1(SCL) U60.A1(SCL) U61.A1(SCL) U61.C3(A1) U63.A1(SCL) ; also on sheet 23 26 39 40 41 42
SOC_I2C1_SDA: U16.A2(SDA) U17.A2(SDA) U58.A2(SDA) U60.A2(SDA) U60.B3(A0) U61.A2(SDA) U61.B3(A0) U63.A2(SDA) ; also on sheet 23 26 39 40 41 42
SW_2V5: L8.1 U57.5(SW)
VMAIN: C391.1 C395.1 C406.1 C410.1 R442.1 U67.8(VIN1) U67.12(VIN2) ; also on sheet 13 14 26
VPP_1V8: C68.2 TP33.1(TP) U18.1(OUT) ; also on sheet 17
VPP_LDO_EN: R103.1 R104.1 ; also on sheet 39
N16839912: C341.1 R391.1 U58.D3(IN+)
N16839940: C371.1 R408.1 U61.D3(IN+)
N16839975: C358.1 R396.1 U60.D3(IN+)
N17012627: R385.2 U57.1(EN)
N17140854: R383.2 U56.3(EN)
N17153379: R92.2 R106.1
N17153381: R96.2 R106.4
N17153415: R136.1 R415.2
N17153417: R136.4 R413.2
N17153507: R84.2 R101.1
N17153509: R87.2 R101.4
N17153511: C58.2 R87.1 U16.D1(BUS) U16.D2(IN-)
N17153515: C58.1 R84.1 U16.D3(IN+)
N17153617: R121.1 R391.2
N17153619: R121.4 R388.2
N17153623: R134.1 R408.2
N17153625: R134.4 R410.2
N17153667: R129.1 R396.2
N17153669: R129.4 R399.2
N17153681: C65.1 R92.1 U17.D3(IN+)
N17153685: C65.2 R96.1 U17.D1(BUS) U17.D2(IN-)
N17153701: C374.2 R413.1 U63.D1(BUS) U63.D2(IN-)
N17153703: C374.1 R415.1 U63.D3(IN+)
N17153749: C341.2 R388.1 U58.D1(BUS) U58.D2(IN-)
N17153787: C371.2 R410.1 U61.D1(BUS) U61.D2(IN-)
N17153799: C358.2 R399.1 U60.D1(BUS) U60.D2(IN-)
N17153878: R414.1 U63.A3(ALERT)
N17153949: R392.1 U58.A3(ALERT)
N17153951: R409.1 U61.A3(ALERT)
N17154063: R397.1 U60.A3(ALERT)
N17277957: C396.1 R444.2
N17337952: R103.2 U18.3(EN)
N18516151: R95.1 U17.A3(ALERT)
N18520654: R85.1 U16.A3(ALERT)

Not connected (* = marked no-connect by the designer): U16 B2(NC1)* C2(NC2)*; U17 B2(NC1)* C2(NC2)*; U58 B2(NC1)* C2(NC2)*; U60 B2(NC1)* C2(NC2)*; U61 B2(NC1)* C2(NC2)*; U63 B2(NC1)* C2(NC2)*

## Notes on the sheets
sheet 15
- PERIPHERAL POWER SUPPLIES - 2
- 3.3V, 6.0 AMPS SUPPLY
- VinMin = 4.5V
  VinMax = 15V
  Vout = 3.3V @ 6A
- SYSTEM PERIPHERAL
- D-Note:-
  Add a Jumper or OR for isolation
  or Current measurement for
  preproduction board
- CAD Note:- Tie the feedback
  after the bulk caps
- SILK SCREEN : VCC_3V3_MAIN
- @@ ALWAYS ON
- PERIPHERAL SUPPLY - ETHERNET PHY
- 2.5V, 1.0 AMP SUPPLY
- 1.8V VPP, 0.5 AMP SUPPLY
- D-Note :-
  It is very important to select
  an LDO with very fast transient
  response and connect its output
  to the VPP pin with a low loop
  inductance path to ensure it
  is able to source the high
  transient load, where the VPP
  pin never drops below the
  minimum operating voltage.
- ETHERNET PHY
- D-Note:- Add a series resistor to the VPP
   supply pin for isolation or testing
- SoC eFUSE
- SILK SCREEN : VDD_2V5
- CAD Note:- Move
  pulldown near to
  EN pin - pin 3 of
  LDO
- D-Note:- Add an additional  decap 0.1 uF
  near to the SoC VPP pin
- D-Note :-
  Alternate part suggestion
  TPS7A21-Q1, Automotive, 500mA,
  low-noise ultra-low-IQ high-PSRR
  low-dropout (LDO) voltage
  regulator
- D-Note :-
  An alternative way to source the VPP is to use
  an external supply. The required caps and
  termination/Discharge resistor are recommended
  to be placed near to the SoC VPP pin.  SOC GPIO
  output can be used to control or time the
  external power supply output
- PERIPHERAL SUPPLY - ETHERNET PHY
- D-Note :-
  Given the transient current requirement during eFuse
  programming, using load switch or FET switch may not be a
  recommended approach,
  It is recommended to use an LDO.  A load or FET switch is
  likely to have too much voltage drop that can't be compensated
  like when using an LDO.
- 1.0V, 0.5 AMP
- SILK SCREEN : VDD_1V0
sheet 16
- CURRENT MONITORING DEVICES
- D-Note:-
- Note the supply rail name change across the shunt when optimizing
  the design (Deleting the current sense resistor)
- VDD_CORE
- SoC_DVDD1V8
- CAD Note:
  Follow Kelvin
  connection
  for Current
  Sensing  when
  using 2
  terminal
  resistors
- I2C ADDRESS: 0x40
- I2C ADDRESS: 0x45
- VDDR_CORE
- VDDA_1V8
- I2C ADDRESS: 0x4E
- I2C ADDRESS: 0x41
- SoC_DVDD3V3
- VDD_LPDDR4
- I2C ADDRESS: 0x4C
- I2C ADDRESS: 0x46
- INA I2C SLAVE ADDRESS
- SLAVE
  ADDRESS
  (IN HEX)
- SUPPLY NET
- POWER SOURCE
- VCC_CORE
- VDD_CORE
- 40
- VCC_0V85
- VDDR_CORE
- 41
- VCC_3V3_SYS
- SoC_DVDD3V3
- 4C
- VCC_1V8
- SoC_DVDD1V8
- 45
- VDDA1V8
- VDDA_1V8
- 4E
- VCC1V1
- VDD_LPDDR4
- 46
